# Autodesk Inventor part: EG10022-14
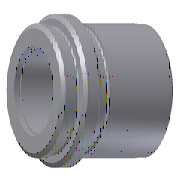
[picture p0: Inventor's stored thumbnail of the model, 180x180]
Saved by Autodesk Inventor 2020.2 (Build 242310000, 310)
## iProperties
Manager: www.cadconsulting.pl
Company: Fabian Stasiak CAD Consulting
Created: 2014-02
Part Number: EG10022-14
Material: DIN 1.7131
Description: Leader Pin Bushings
Document SubType Name: Modeling
Designer: F.Stasiak
Standard Revision: 1
Manufacturer: DME
Language: pl-PL
Size Designation: 22-14
Categories: <MemberInstance><Categories><Category DisplayName="Forma wtryskowa" InternalName="349578f2-f4d4-4954-8c09-8e99297a61c0" Mnemonic="MOLD"><Category DisplayName="K
Density: 7.85 g/cm^3
Appearance: Domyślna
Catalog Web Link: www.expertbooks.pl
IsCustomPart: 0
Author: F.Stasiak
Subject: Zbiór ćwiczeń. Autodesk Inventor 2020. Kurs Professional
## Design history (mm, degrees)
sketch "Sketch1"
  geometry: L1 (0, -16.8)-(0, 9.8) reference; L2 (0, 15)-(10, 15); L3 (10, 15)-(10, 7); L4 (10, 7)-(9.5, 7); L5 (9.5, 7)-(9.5, 6); L6 (9.5, 6)-(12.5, 6); L7 (12.5, 6)-(12.5, 0); L8 (12.5, 0)-(9.5, 0); L9 (9.5, 0)-(9.5, -1); L10 (9.5, -1)-(10, -1); L11 (10, -1)-(10, -15); L12 (10, -15)-(9.95, -15); L13 (9.95, -15)-(9.95, -16); L14 (9.95, -16)-(0, -16); L15 (0, 15)-(0, -16); 1 further point
  constraints: 28 end point, 7 parallel, 5 perpendicular, 2 collinear, 2 equal length, 2 point on line, 1 horizontal alignment
  dimensions: "d0" = 20 diameter of L11 L1 (= D); "d2" = 1 distance between parallel lines of L14 L12; "d27" = 19.9 diameter of L13 L1 (= D_Guide); "d4" = 25 diameter of L7 L1 (= D2); "d5" = 20 diameter of L3 L1 (= D1); "d6" = 6 distance between parallel lines of L8 L6 (= H_); "d7" = 22 distance between parallel lines of L14 L6 (= L); "d8" = 9 distance between parallel lines of L6 L2 (= L1); "d9" = 1 distance between parallel lines of L10 L8; "d10" = 0.5 distance between parallel lines of L11 L9
revolve "Revolution1" sketch "Sketch1" stored, may be unused: angle "d11" = 90 deg
sketch "Sketch2"
  geometry: L1 (-9.95, -16)-(9.95, -16) reference; L2 (7, -16)-(7, 6); L3 (7, 6)-(7, 6); L4 (7, 6)-(7, 37); L5 (0, -16)-(0, 37); L6 (0, 37)-(7, 37); L7 (7, -16)-(0, -16)
  constraints: 12 end point, 3 perpendicular, 2 collinear, 1 midpoint, 1 parallel, 1 point on line
  dimensions: "d12" = 14 diameter of L2 L5 (= d_); "d13" = 22 distance of L2.start L2.end (= l_); "d14" = 31 distance of L3.end L4.end (= L + L1); "d15" = 14 diameter of L4 L5 (= d3)
revolve "Revolution2" sketch "Sketch2" stored, may be unused: angle "d16" = 90 deg
chamfer "Chamfer1" distance "d17" = 0.5; stored, may be unused: second distance "d18" = 2, angle "d19" = 45 deg
fillet "Fillet1" dims "d20" = 0.3
fillet "Fillet2" dims "d21" = 0.8
body "Solid1"
other parameters: "d_" = 14 [user parameter; used in 1 equation term], "L" = 22 [user parameter; used in 2 equation terms], "D" = 20 [user parameter; used in 1 equation term], "D1" = 20 [user parameter; used in 1 equation term], "D2" = 25 [user parameter; used in 1 equation term], "H_" = 6 [user parameter; used in 1 equation term], "L1" = 9 [user parameter; used in 2 equation terms], "l_" = 22 [user parameter; used in 1 equation term], "d3" = 14 [user parameter; used in 1 equation term], "D_Guide" = 19.9 [user parameter; used in 1 equation term], "d22" = 0, "d23" = 0, "d24" = 0, "d25" = 0, "d26" = 0
